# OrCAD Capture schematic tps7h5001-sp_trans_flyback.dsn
size Custom; title: TPS7H5001-SP Radiation-Hardness-Assured Si and GaN; rev: *; note: Datasheet: SLVSF07    EVM User Guide: SLVUBZ8; note: Dual Output Controller
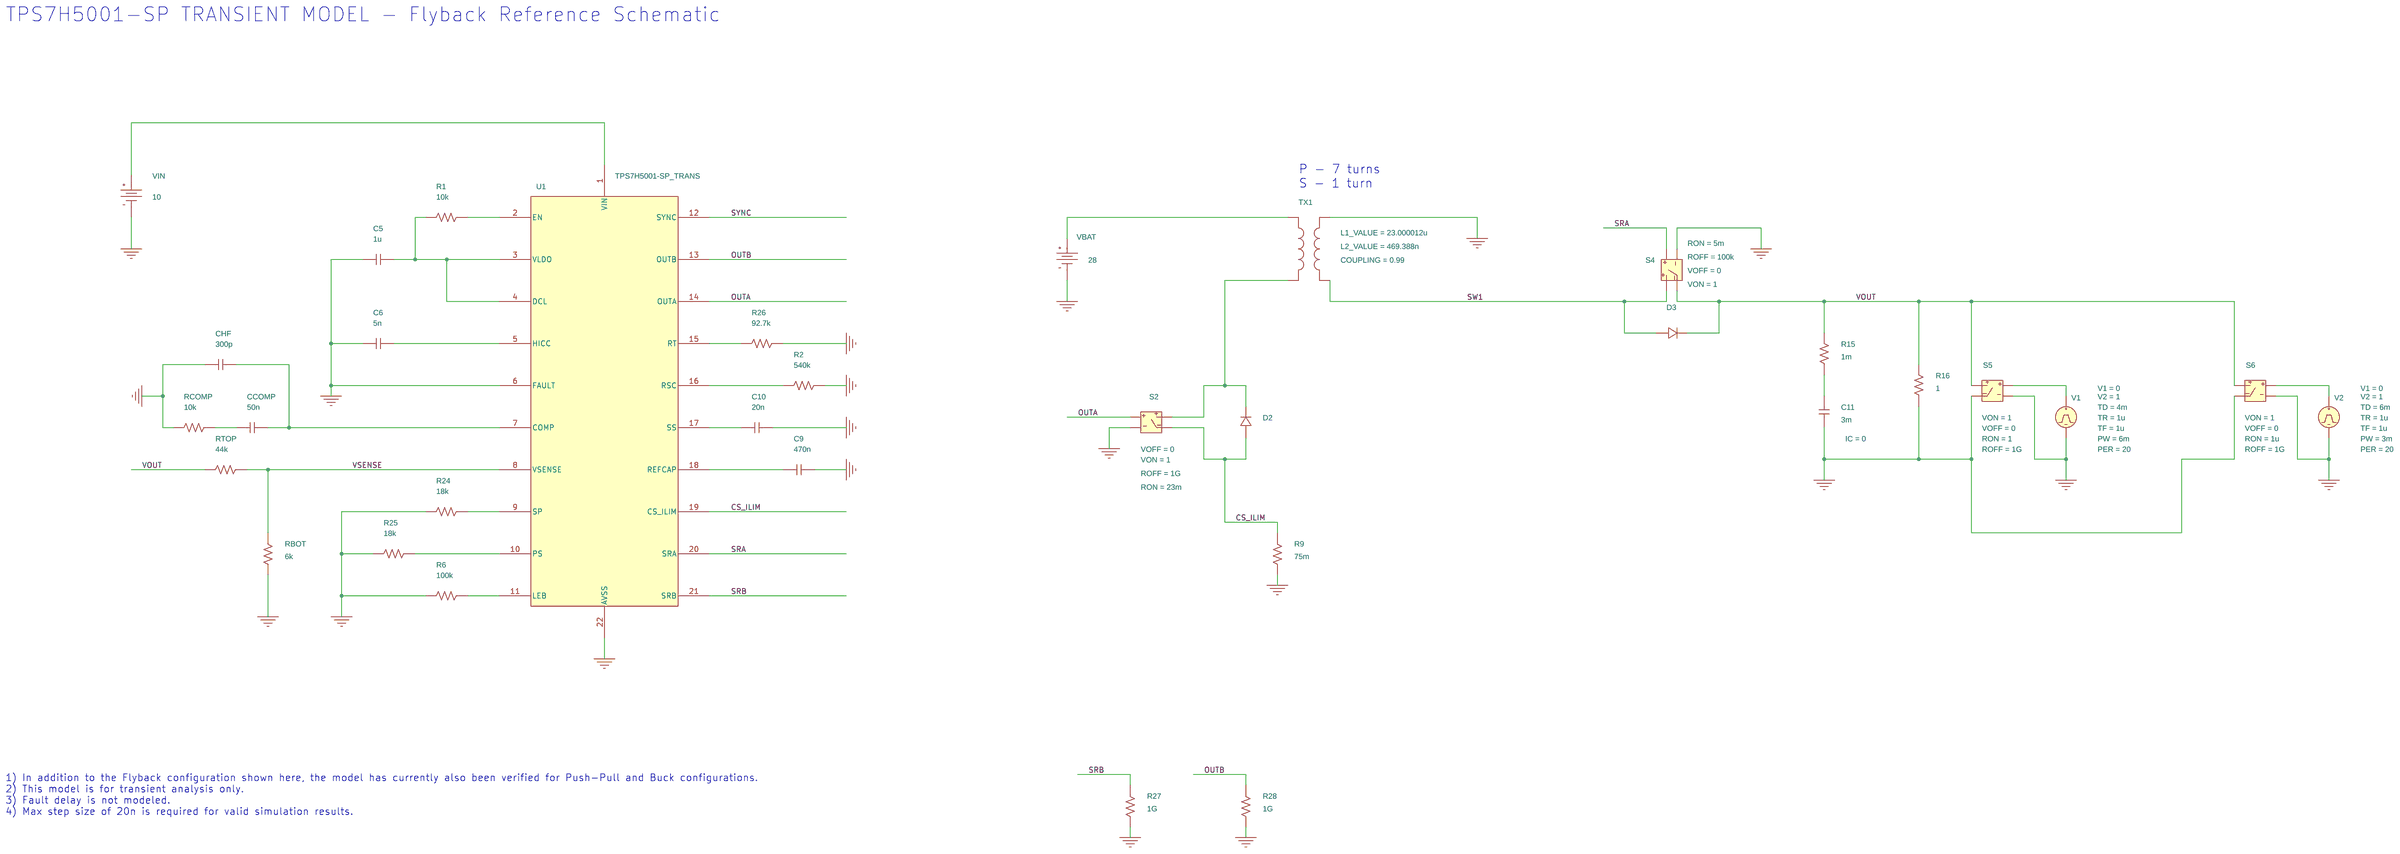
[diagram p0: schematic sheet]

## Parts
C5  1u  [cap196]
C6  5n  [cap196]
C9  470n  [cap196]
C10  20n  [cap196]
C11  3m  [cap196]
CCOMP  50n  [cap196]
CHF  300p  [cap196]
D2  Dbreak
D3  Dbreak
R1  10k  [AXRC05]
R2  540k  [AXRC05]
R6  100k  [AXRC05]
R9  75m  [AXRC05]
R15  1m  [AXRC05]
R16  1  [AXRC05]
R24  18k  [AXRC05]
R25  18k  [AXRC05]
R26  92.7k  [AXRC05]
R27  1G  [AXRC05]
R28  1G  [AXRC05]
RBOT  6k  [AXRC05]
RCOMP  10k  [AXRC05]
RTOP  44k  [AXRC05]
S2  S
S4  S
S5  S
S6  S
TX1  XFRM_LINEAR
U1  TPS7H5001-SP_TRANS
V1  VPULSE
V2  VPULSE
VBAT  VDC
VIN  VDC

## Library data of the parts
C5 C6 C9 C10 CCOMP CHF = C
C11 = C: IC: 0
D2 D3 = Dbreak
R1 R2 R6 R9 R15 R16 R24-R28 RBOT RCOMP RTOP = R
S2 = S: ROFF: 1G; RON: 23m; VOFF: 0; VON: 1
S4 = S: ROFF: 100k; RON: 5m; VOFF: 0; VON: 1
S5 = S: ROFF: 1G; RON: 1; VOFF: 0; VON: 1
S6 = S: ROFF: 1G; RON: 1u; VOFF: 0; VON: 1
TX1 = XFRM_LINEAR: COUPLING: 0.99; L1_VALUE: 23.000012u; L2_VALUE: 469.388n
U1 = TPS7H5001-SP_TRANS_3: PSpiceTemplate: X^@REFDES  %VIN %EN %VLDO %DCL %HICC %FAULT %COMP %VSENSE %SP %PS %LEB %SYNC %OUTB %OUTA %RT %RSC %SS %REFCAP %CS_ILIM %SRA %SRB %AVSS @MODEL
V1 = VPULSE: PER: 20; PW: 6m; TD: 4m; TF: 1u; TR: 1u; V1: 0; V2: 1
V2 = VPULSE: PER: 20; PW: 3m; TD: 6m; TF: 1u; TR: 1u; V1: 0; V2: 1
VBAT = VDC: DC: 28
VIN = VDC: DC: 10

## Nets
0: C5.2 C6.2 C9.1 C10.1 C11.1 CHF.2 R2.1 R6.2 R9.2 R16.1 R24.2 R25.2 R26.1 R27.2 R28.2 RBOT.2 RCOMP.2 S2.1(2) S4.1(2) S5.1(2) S5.3(4) S6.1(2) S6.3(4) TX1.3 U1.6(FAULT) U1.22(AVSS) V1.2(-) V2.2(-) VBAT.1(-) VIN.1(-)
CS_ILIM: D2.0(1) R9.1 S2.3(4) U1.19(CS_ILIM)
OUTA: S2.0(1) U1.14(OUTA)
OUTB: R28.1 U1.13(OUTB)
SRA: S4.0(1) U1.20(SRA)
SRB: R27.1 U1.21(SRB)
SW1: D3.0(1) S4.2(3) TX1.4
SYNC: U1.12(SYNC)
VOUT: D3.1(2) R15.2 R16.2 RTOP.2 S4.3(4) S5.2(3) S6.2(3)
VSENSE: RBOT.1 RTOP.1 U1.8(VSENSE)
N16776927: U1.1(VIN) VIN.0(+)
N16776997: C5.1 R1.2 U1.3(VLDO) U1.4(DCL)
N16777005: R1.1 U1.2(EN)
N16777147: C6.1 U1.5(HICC)
N16777153: R26.2 U1.15(RT)
N16777193: CCOMP.1 CHF.1 U1.7(COMP)
N16777233: R2.2 U1.16(RSC)
N16777279: CCOMP.2 RCOMP.1
N16777287: C10.2 U1.17(SS)
N16777327: C9.2 U1.18(REFCAP)
N16777348: R24.1 U1.9(SP)
N16777380: R25.1 U1.10(PS)
N16777405: R6.1 U1.11(LEB)
N16778445: TX1.1 VBAT.0(+)
N16778529: D2.1(2) S2.2(3) TX1.2
N16778604: C11.2 R15.1
N16778665: S5.0(1) V1.1(+)
N16778670: S6.0(1) V2.1(+)

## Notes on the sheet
- TPS7H5001-SP TRANSIENT MODEL - Flyback Reference Schematic
- P - 7 turns
  S - 1 turn
- 1) In addition to the Flyback configuration shown here, the model has currently also been verified for Push-Pull and Buck configurations.
  2) This model is for transient analysis only.
  3) Fault delay is not modeled.
  4) Max step size of 20n is required for valid simulation results.
